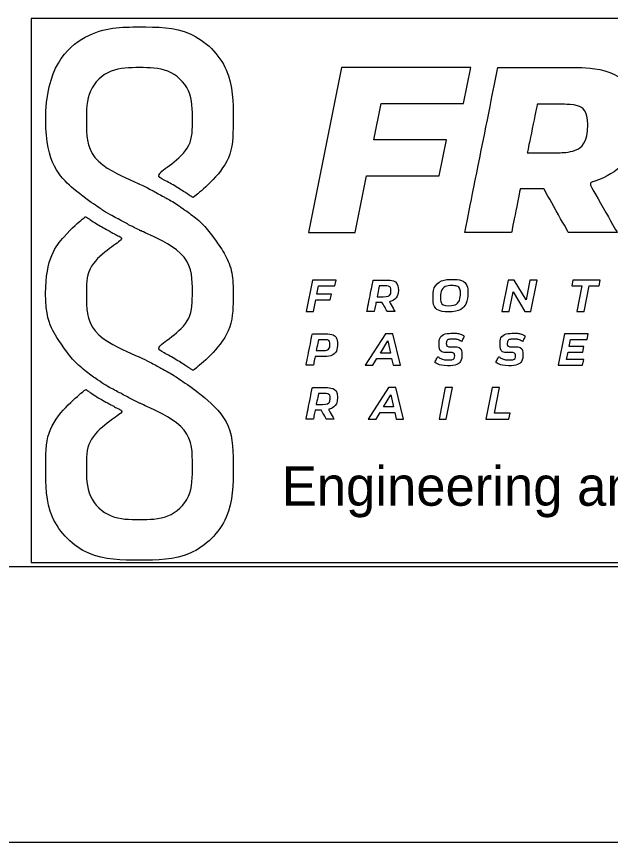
# Model space of a CAD drawing. Extents: x 0 to 1.42, y 0 to 0.92.
# Drawn here: x 0.6182 to 0.7078, y 0 to 0.1247 of the extents above; entities that cross this region are included whole.
import ezdxf

# ---------------------------------------------------------------- set-up
doc = ezdxf.new("R2010")
doc.units = 0
for name, color, linetype in [('DRAFT_Information-No Plot', 7, 'Continuous'), ('DRAFT_Miscellaneous-Blue', 7, 'Continuous'), ('DRAFT_Miscellaneous-Grey', 7, 'Continuous'), ('DRAFT_Miscellaneous-White', 7, 'Continuous'), ('SHEET_Lines', 7, 'Continuous'), ('SHEET_Plot Boundary', 7, 'Continuous')]:
    doc.layers.add(name, color=color, linetype=linetype)

msp = doc.modelspace()

# ---------------------------------------------------------------- linework, layer by layer
at = {"layer": 'DRAFT_Information-No Plot'}
msp.add_lwpolyline([(0.62039, 0.04226), (0.78383, 0.04226), (0.78383, 0.12437), (0.62039, 0.12437), (0.62039, 0.04226)], dxfattribs=at)
at = {"layer": 'DRAFT_Miscellaneous-Blue'}
for p, q in [((0.62258, 0.10897), (0.62258, 0.10897)), ((0.62257, 0.08286), (0.62257, 0.08286))]:
    msp.add_line(p, q, dxfattribs=at)
for points in [[(0.68563, 0.11154), (0.68673, 0.11699), (0.66722, 0.11699), (0.66223, 0.09206), (0.66928, 0.09206), (0.67099, 0.10061), (0.68196, 0.10061), (0.68307, 0.10606), (0.67206, 0.10606), (0.67317, 0.11154)], [(0.66621, 0.08403), (0.66639, 0.08491), (0.66281, 0.08491), (0.66186, 0.08017), (0.66297, 0.08017), (0.66331, 0.0819), (0.6655, 0.0819), (0.66568, 0.08278), (0.66348, 0.08278), (0.66373, 0.08403)], [(0.69563, 0.08491), (0.69504, 0.08194), (0.69327, 0.08491), (0.69236, 0.08491), (0.69141, 0.08017), (0.6925, 0.08017), (0.69309, 0.08314), (0.69486, 0.08017), (0.69576, 0.08017), (0.69671, 0.08491)], [(0.70269, 0.08017), (0.70379, 0.08017), (0.70456, 0.08402), (0.70607, 0.08402), (0.70625, 0.08491), (0.70212, 0.08491), (0.70194, 0.08402), (0.70346, 0.08402)], [(0.675, 0.07205), (0.67609, 0.07205), (0.67493, 0.07679), (0.67384, 0.07679), (0.67078, 0.07205), (0.67195, 0.07205), (0.67256, 0.07306), (0.67477, 0.07306)], [(0.70426, 0.07591), (0.70444, 0.07679), (0.70086, 0.07679), (0.69991, 0.07205), (0.70358, 0.07205), (0.70376, 0.07293), (0.70117, 0.07293), (0.70139, 0.07402), (0.7036, 0.07402), (0.70377, 0.07488), (0.70157, 0.07488), (0.70177, 0.07591)], [(0.67307, 0.07389), (0.67419, 0.07572), (0.67459, 0.07389)], [(0.67547, 0.06392), (0.67656, 0.06392), (0.6754, 0.06866), (0.67432, 0.06866), (0.67125, 0.06392), (0.67242, 0.06392), (0.67304, 0.06493), (0.67524, 0.06493)], [(0.68192, 0.06392), (0.68302, 0.06392), (0.68397, 0.06866), (0.68287, 0.06866)], [(0.68899, 0.06392), (0.69247, 0.06392), (0.69265, 0.06481), (0.69027, 0.06481), (0.69104, 0.06866), (0.68994, 0.06866)], [(0.67354, 0.06577), (0.67466, 0.0676), (0.67506, 0.06577)]]:
    msp.add_lwpolyline(points, close=True, dxfattribs=at)
for points in [[(0.62258, 0.10897), (0.62258, 0.10256), (0.62703, 0.09826), (0.63047, 0.09592), (0.63158, 0.09517), (0.63291, 0.09442), (0.63359, 0.09408), (0.63538, 0.0931), (0.63663, 0.09248), (0.63673, 0.09243), (0.6372, 0.09221), (0.64471, 0.08876), (0.64471, 0.08286), (0.64471, 0.07897), (0.64144, 0.07614), (0.63908, 0.07461), (0.64035, 0.07396), (0.6423, 0.0729), (0.64416, 0.07167), (0.64416, 0.07167), (0.64483, 0.07124), (0.64483, 0.07124), (0.64781, 0.07374), (0.65085, 0.07758), (0.65085, 0.08286), (0.65085, 0.08607), (0.64973, 0.08875), (0.64818, 0.09092), (0.64665, 0.09307), (0.64468, 0.09473), (0.64297, 0.0959), (0.64297, 0.0959), (0.64296, 0.09591), (0.64295, 0.09592), (0.64295, 0.09592), (0.64294, 0.09592), (0.64293, 0.09593), (0.64192, 0.09662), (0.64101, 0.09714), (0.64032, 0.0975), (0.64029, 0.09751), (0.64028, 0.09752), (0.64025, 0.09753), (0.6383, 0.09865), (0.63671, 0.0994), (0.63671, 0.0994), (0.63647, 0.09951), (0.62872, 0.10298), (0.62872, 0.10897), (0.62872, 0.11367), (0.6323, 0.11697), (0.63672, 0.11697), (0.64114, 0.11697), (0.64472, 0.11372), (0.64472, 0.10897), (0.64472, 0.10507), (0.64144, 0.10224), (0.63908, 0.10071), (0.64036, 0.10006), (0.6423, 0.099), (0.64416, 0.09777), (0.64416, 0.09777), (0.64483, 0.09734), (0.64483, 0.09734), (0.64782, 0.09984), (0.65086, 0.10368), (0.65086, 0.10897), (0.65086, 0.1169), (0.64464, 0.12311), (0.63672, 0.12311), (0.62878, 0.12311), (0.62258, 0.1169), (0.62258, 0.10897)], [(0.71148, 0.10905), (0.71148, 0.11403), (0.70781, 0.11699), (0.70144, 0.11699), (0.70144, 0.11699), (0.69079, 0.11699), (0.69079, 0.11699), (0.69079, 0.11699), (0.68581, 0.09206), (0.68581, 0.09206), (0.68581, 0.09206), (0.69286, 0.09206), (0.69286, 0.09206), (0.69286, 0.09206), (0.69417, 0.09869), (0.69417, 0.09869), (0.69417, 0.09869), (0.69774, 0.09869), (0.69774, 0.09869), (0.69774, 0.09869), (0.70144, 0.09206), (0.70144, 0.09206), (0.70144, 0.09206), (0.70881, 0.09206), (0.70881, 0.09206), (0.70881, 0.09206), (0.70457, 0.09954), (0.70457, 0.09954), (0.70892, 0.10104), (0.71148, 0.10445), (0.71148, 0.10905)], [(0.70436, 0.10837), (0.70436, 0.10563), (0.70254, 0.10413), (0.69944, 0.10413), (0.69944, 0.10413), (0.69524, 0.10413), (0.69524, 0.10413), (0.69524, 0.10413), (0.69674, 0.11143), (0.69674, 0.11143), (0.69674, 0.11143), (0.70044, 0.11143), (0.70044, 0.11143), (0.70286, 0.11143), (0.70436, 0.11047), (0.70436, 0.10837)], [(0.62257, 0.08286), (0.62258, 0.07965), (0.62369, 0.07698), (0.62524, 0.07481), (0.62679, 0.07264), (0.62876, 0.07098), (0.63048, 0.0698), (0.63167, 0.06899), (0.63281, 0.06836), (0.63353, 0.06801), (0.63543, 0.06697), (0.63674, 0.06632), (0.63674, 0.06632), (0.63721, 0.06611), (0.64472, 0.06266), (0.64472, 0.05676), (0.64472, 0.05201), (0.64114, 0.04876), (0.63672, 0.04876), (0.6323, 0.04876), (0.62872, 0.05206), (0.62872, 0.05676), (0.62872, 0.06066), (0.63201, 0.0635), (0.63437, 0.06502), (0.63389, 0.06528), (0.6333, 0.06559), (0.63262, 0.06596), (0.63262, 0.06596), (0.63221, 0.06619), (0.63213, 0.06623), (0.63013, 0.06734), (0.62924, 0.06796), (0.62923, 0.06797), (0.62923, 0.06797), (0.62861, 0.0684), (0.62861, 0.0684), (0.62561, 0.0659), (0.62258, 0.06204), (0.62258, 0.05676), (0.62258, 0.04883), (0.62878, 0.04262), (0.63672, 0.04262), (0.64464, 0.04262), (0.65086, 0.04883), (0.65086, 0.05676), (0.65086, 0.06318), (0.64638, 0.06747), (0.64294, 0.06983), (0.64185, 0.07057), (0.64087, 0.07112), (0.64017, 0.07148), (0.63825, 0.07257), (0.63671, 0.07329), (0.63671, 0.07329), (0.63671, 0.07329), (0.62872, 0.07678), (0.62871, 0.08286), (0.62872, 0.08677), (0.632, 0.0896), (0.63437, 0.09113), (0.63383, 0.09141), (0.63315, 0.09177), (0.63237, 0.0922), (0.6302, 0.09339), (0.62924, 0.09406), (0.62923, 0.09406), (0.62923, 0.09406), (0.62859, 0.09449), (0.62859, 0.09449), (0.62561, 0.09199), (0.62258, 0.08814), (0.62257, 0.08286)], [(0.67578, 0.08344), (0.67578, 0.08437), (0.6751, 0.08491), (0.67392, 0.08491), (0.67392, 0.08491), (0.67199, 0.08491), (0.67199, 0.08491), (0.67199, 0.08491), (0.67104, 0.08017), (0.67104, 0.08017), (0.67104, 0.08017), (0.67215, 0.08017), (0.67215, 0.08017), (0.67215, 0.08017), (0.67241, 0.0815), (0.67241, 0.0815), (0.67241, 0.0815), (0.67335, 0.0815), (0.67335, 0.0815), (0.67335, 0.0815), (0.67409, 0.08017), (0.67409, 0.08017), (0.67409, 0.08017), (0.67525, 0.08017), (0.67525, 0.08017), (0.67525, 0.08017), (0.67442, 0.08164), (0.67442, 0.08164), (0.67527, 0.0819), (0.67578, 0.08255), (0.67578, 0.08344)], [(0.68332, 0.08009), (0.68507, 0.08009), (0.68626, 0.08132), (0.68626, 0.08294), (0.68626, 0.08415), (0.68539, 0.08499), (0.68395, 0.08499), (0.6822, 0.08499), (0.68101, 0.08377), (0.68101, 0.08215), (0.68101, 0.08093), (0.68188, 0.08009), (0.68332, 0.08009)], [(0.67351, 0.08237), (0.67351, 0.08237), (0.67258, 0.08237), (0.67258, 0.08237), (0.67258, 0.08237), (0.67291, 0.08402), (0.67291, 0.08402), (0.67291, 0.08402), (0.67378, 0.08402), (0.67378, 0.08402), (0.67434, 0.08402), (0.67467, 0.0838), (0.67467, 0.08334), (0.67467, 0.08271), (0.67424, 0.08237), (0.67351, 0.08237)], [(0.68342, 0.08103), (0.68258, 0.08103), (0.68212, 0.08151), (0.68212, 0.08221), (0.68212, 0.08321), (0.68278, 0.08406), (0.68385, 0.08406), (0.68468, 0.08406), (0.68515, 0.08358), (0.68515, 0.08287), (0.68515, 0.08187), (0.68449, 0.08103), (0.68342, 0.08103)], [(0.66473, 0.07679), (0.66473, 0.07679), (0.66281, 0.07679), (0.66281, 0.07679), (0.66281, 0.07679), (0.66186, 0.07205), (0.66186, 0.07205), (0.66186, 0.07205), (0.66297, 0.07205), (0.66297, 0.07205), (0.66297, 0.07205), (0.66322, 0.07335), (0.66322, 0.07335), (0.66322, 0.07335), (0.66428, 0.07335), (0.66428, 0.07335), (0.66569, 0.07335), (0.66658, 0.0741), (0.66658, 0.07531), (0.66658, 0.07624), (0.66591, 0.07679), (0.66473, 0.07679)], [(0.68318, 0.07196), (0.68451, 0.07196), (0.68537, 0.07259), (0.68537, 0.07358), (0.68537, 0.07503), (0.68301, 0.07463), (0.68302, 0.0754), (0.68302, 0.07574), (0.68339, 0.07599), (0.68403, 0.07599), (0.6845, 0.07599), (0.68496, 0.07587), (0.68532, 0.07562), (0.68532, 0.07562), (0.68573, 0.07646), (0.68573, 0.07646), (0.68532, 0.07672), (0.68473, 0.07687), (0.68409, 0.07687), (0.68278, 0.07687), (0.68193, 0.07624), (0.68193, 0.07526), (0.68193, 0.07375), (0.68428, 0.07416), (0.68428, 0.0734), (0.68428, 0.07305), (0.6839, 0.07284), (0.68329, 0.07284), (0.68273, 0.07284), (0.68216, 0.07302), (0.68173, 0.07334), (0.68173, 0.07334), (0.68128, 0.07249), (0.68128, 0.07249), (0.68168, 0.07219), (0.68241, 0.07196), (0.68318, 0.07196)], [(0.69238, 0.07196), (0.6937, 0.07196), (0.69457, 0.07259), (0.69457, 0.07358), (0.69457, 0.07503), (0.69221, 0.07463), (0.69222, 0.0754), (0.69222, 0.07574), (0.69259, 0.07599), (0.69323, 0.07599), (0.6937, 0.07599), (0.69416, 0.07587), (0.69452, 0.07562), (0.69452, 0.07562), (0.69493, 0.07646), (0.69493, 0.07646), (0.69452, 0.07672), (0.69393, 0.07687), (0.69329, 0.07687), (0.69198, 0.07687), (0.69112, 0.07624), (0.69112, 0.07526), (0.69112, 0.07375), (0.69347, 0.07416), (0.69347, 0.0734), (0.69347, 0.07305), (0.69309, 0.07284), (0.69249, 0.07284), (0.69193, 0.07284), (0.69136, 0.07302), (0.69093, 0.07334), (0.69093, 0.07334), (0.69048, 0.07249), (0.69048, 0.07249), (0.69088, 0.07219), (0.69161, 0.07196), (0.69238, 0.07196)], [(0.66433, 0.07425), (0.66433, 0.07425), (0.6634, 0.07425), (0.6634, 0.07425), (0.6634, 0.07425), (0.66373, 0.07589), (0.66373, 0.07589), (0.66373, 0.07589), (0.66459, 0.07589), (0.66459, 0.07589), (0.66515, 0.07589), (0.66547, 0.07568), (0.66547, 0.07521), (0.66547, 0.07458), (0.66505, 0.07425), (0.66433, 0.07425)], [(0.66659, 0.06719), (0.66659, 0.06812), (0.66592, 0.06866), (0.66474, 0.06866), (0.66474, 0.06866), (0.66281, 0.06866), (0.66281, 0.06866), (0.66281, 0.06866), (0.66186, 0.06392), (0.66186, 0.06392), (0.66186, 0.06392), (0.66297, 0.06392), (0.66297, 0.06392), (0.66297, 0.06392), (0.66323, 0.06525), (0.66323, 0.06525), (0.66323, 0.06525), (0.66416, 0.06525), (0.66416, 0.06525), (0.66416, 0.06525), (0.66491, 0.06392), (0.66491, 0.06392), (0.66491, 0.06392), (0.66607, 0.06392), (0.66607, 0.06392), (0.66607, 0.06392), (0.66524, 0.06538), (0.66524, 0.06538), (0.66609, 0.06565), (0.66659, 0.06629), (0.66659, 0.06719)], [(0.66433, 0.06612), (0.66433, 0.06612), (0.6634, 0.06612), (0.6634, 0.06612), (0.6634, 0.06612), (0.66373, 0.06777), (0.66373, 0.06777), (0.66373, 0.06777), (0.6646, 0.06777), (0.6646, 0.06777), (0.66516, 0.06777), (0.66548, 0.06755), (0.66548, 0.06709), (0.66548, 0.06646), (0.66506, 0.06612), (0.66433, 0.06612)]]:
    msp.add_open_spline(points, degree=3, dxfattribs=at)
at = {"layer": 'DRAFT_Miscellaneous-White'}
for points in [[(0.68563, 0.11154), (0.68673, 0.11699), (0.66722, 0.11699), (0.66223, 0.09206), (0.66928, 0.09206), (0.67099, 0.10061), (0.68196, 0.10061), (0.68307, 0.10606), (0.67206, 0.10606), (0.67317, 0.11154), (0.68563, 0.11154)], [(0.66621, 0.08403), (0.66639, 0.08491), (0.66281, 0.08491), (0.66186, 0.08017), (0.66297, 0.08017), (0.66331, 0.0819), (0.6655, 0.0819), (0.66568, 0.08278), (0.66348, 0.08278), (0.66373, 0.08403), (0.66621, 0.08403)], [(0.69563, 0.08491), (0.69504, 0.08194), (0.69327, 0.08491), (0.69236, 0.08491), (0.69141, 0.08017), (0.6925, 0.08017), (0.69309, 0.08314), (0.69486, 0.08017), (0.69576, 0.08017), (0.69671, 0.08491), (0.69563, 0.08491)], [(0.70269, 0.08017), (0.70379, 0.08017), (0.70456, 0.08402), (0.70607, 0.08402), (0.70625, 0.08491), (0.70212, 0.08491), (0.70194, 0.08402), (0.70346, 0.08402), (0.70269, 0.08017)], [(0.675, 0.07205), (0.67609, 0.07205), (0.67493, 0.07679), (0.67384, 0.07679), (0.67078, 0.07205), (0.67195, 0.07205), (0.67256, 0.07306), (0.67477, 0.07306), (0.675, 0.07205)], [(0.70426, 0.07591), (0.70444, 0.07679), (0.70086, 0.07679), (0.69991, 0.07205), (0.70358, 0.07205), (0.70376, 0.07293), (0.70117, 0.07293), (0.70139, 0.07402), (0.7036, 0.07402), (0.70377, 0.07488), (0.70157, 0.07488), (0.70177, 0.07591), (0.70426, 0.07591)], [(0.67307, 0.07389), (0.67419, 0.07572), (0.67459, 0.07389), (0.67307, 0.07389)], [(0.67547, 0.06392), (0.67656, 0.06392), (0.6754, 0.06866), (0.67432, 0.06866), (0.67125, 0.06392), (0.67242, 0.06392), (0.67304, 0.06493), (0.67524, 0.06493), (0.67547, 0.06392)], [(0.68192, 0.06392), (0.68302, 0.06392), (0.68397, 0.06866), (0.68287, 0.06866), (0.68192, 0.06392)], [(0.68899, 0.06392), (0.69247, 0.06392), (0.69265, 0.06481), (0.69027, 0.06481), (0.69104, 0.06866), (0.68994, 0.06866), (0.68899, 0.06392)], [(0.67354, 0.06577), (0.67466, 0.0676), (0.67506, 0.06577), (0.67354, 0.06577)]]:
    msp.add_lwpolyline(points, dxfattribs=at)
for points in [[(0.62258, 0.10897), (0.62258, 0.10256), (0.62703, 0.09826), (0.63047, 0.09592), (0.63158, 0.09517), (0.63291, 0.09442), (0.63359, 0.09408), (0.63538, 0.0931), (0.63663, 0.09248), (0.63673, 0.09243), (0.6372, 0.09221), (0.64471, 0.08876), (0.64471, 0.08286), (0.64471, 0.07897), (0.64144, 0.07614), (0.63908, 0.07461), (0.64035, 0.07396), (0.6423, 0.0729), (0.64416, 0.07167), (0.64416, 0.07167), (0.64483, 0.07124), (0.64483, 0.07124), (0.64781, 0.07374), (0.65085, 0.07758), (0.65085, 0.08286), (0.65085, 0.08607), (0.64973, 0.08875), (0.64818, 0.09092), (0.64665, 0.09307), (0.64468, 0.09473), (0.64297, 0.0959), (0.64297, 0.0959), (0.64296, 0.09591), (0.64295, 0.09592), (0.64295, 0.09592), (0.64294, 0.09592), (0.64293, 0.09593), (0.64192, 0.09662), (0.64101, 0.09714), (0.64032, 0.0975), (0.64029, 0.09751), (0.64028, 0.09752), (0.64025, 0.09753), (0.6383, 0.09865), (0.63671, 0.0994), (0.63671, 0.0994), (0.63647, 0.09951), (0.62872, 0.10298), (0.62872, 0.10897), (0.62872, 0.11367), (0.6323, 0.11697), (0.63672, 0.11697), (0.64114, 0.11697), (0.64472, 0.11372), (0.64472, 0.10897), (0.64472, 0.10507), (0.64144, 0.10224), (0.63908, 0.10071), (0.64036, 0.10006), (0.6423, 0.099), (0.64416, 0.09777), (0.64416, 0.09777), (0.64483, 0.09734), (0.64483, 0.09734), (0.64782, 0.09984), (0.65086, 0.10368), (0.65086, 0.10897), (0.65086, 0.1169), (0.64464, 0.12311), (0.63672, 0.12311), (0.62878, 0.12311), (0.62258, 0.1169), (0.62258, 0.10897)], [(0.71148, 0.10905), (0.71148, 0.11403), (0.70781, 0.11699), (0.70144, 0.11699), (0.70144, 0.11699), (0.69079, 0.11699), (0.69079, 0.11699), (0.69079, 0.11699), (0.68581, 0.09206), (0.68581, 0.09206), (0.68581, 0.09206), (0.69286, 0.09206), (0.69286, 0.09206), (0.69286, 0.09206), (0.69417, 0.09869), (0.69417, 0.09869), (0.69417, 0.09869), (0.69774, 0.09869), (0.69774, 0.09869), (0.69774, 0.09869), (0.70144, 0.09206), (0.70144, 0.09206), (0.70144, 0.09206), (0.70881, 0.09206), (0.70881, 0.09206), (0.70881, 0.09206), (0.70457, 0.09954), (0.70457, 0.09954), (0.70892, 0.10104), (0.71148, 0.10445), (0.71148, 0.10905)], [(0.70436, 0.10837), (0.70436, 0.10563), (0.70254, 0.10413), (0.69944, 0.10413), (0.69944, 0.10413), (0.69524, 0.10413), (0.69524, 0.10413), (0.69524, 0.10413), (0.69674, 0.11143), (0.69674, 0.11143), (0.69674, 0.11143), (0.70044, 0.11143), (0.70044, 0.11143), (0.70286, 0.11143), (0.70436, 0.11047), (0.70436, 0.10837)], [(0.62257, 0.08286), (0.62258, 0.07965), (0.62369, 0.07698), (0.62524, 0.07481), (0.62679, 0.07264), (0.62876, 0.07098), (0.63048, 0.0698), (0.63167, 0.06899), (0.63281, 0.06836), (0.63353, 0.06801), (0.63543, 0.06697), (0.63674, 0.06632), (0.63674, 0.06632), (0.63721, 0.06611), (0.64472, 0.06266), (0.64472, 0.05676), (0.64472, 0.05201), (0.64114, 0.04876), (0.63672, 0.04876), (0.6323, 0.04876), (0.62872, 0.05206), (0.62872, 0.05676), (0.62872, 0.06066), (0.63201, 0.0635), (0.63437, 0.06502), (0.63389, 0.06528), (0.6333, 0.06559), (0.63262, 0.06596), (0.63262, 0.06596), (0.63221, 0.06619), (0.63213, 0.06623), (0.63013, 0.06734), (0.62924, 0.06796), (0.62923, 0.06797), (0.62923, 0.06797), (0.62861, 0.0684), (0.62861, 0.0684), (0.62561, 0.0659), (0.62258, 0.06204), (0.62258, 0.05676), (0.62258, 0.04883), (0.62878, 0.04262), (0.63672, 0.04262), (0.64464, 0.04262), (0.65086, 0.04883), (0.65086, 0.05676), (0.65086, 0.06318), (0.64638, 0.06747), (0.64294, 0.06983), (0.64185, 0.07057), (0.64087, 0.07112), (0.64017, 0.07148), (0.63825, 0.07257), (0.63671, 0.07329), (0.63671, 0.07329), (0.63671, 0.07329), (0.62872, 0.07678), (0.62871, 0.08286), (0.62872, 0.08677), (0.632, 0.0896), (0.63437, 0.09113), (0.63383, 0.09141), (0.63315, 0.09177), (0.63237, 0.0922), (0.6302, 0.09339), (0.62924, 0.09406), (0.62923, 0.09406), (0.62923, 0.09406), (0.62859, 0.09449), (0.62859, 0.09449), (0.62561, 0.09199), (0.62258, 0.08814), (0.62257, 0.08286)], [(0.67578, 0.08344), (0.67578, 0.08437), (0.6751, 0.08491), (0.67392, 0.08491), (0.67392, 0.08491), (0.67199, 0.08491), (0.67199, 0.08491), (0.67199, 0.08491), (0.67104, 0.08017), (0.67104, 0.08017), (0.67104, 0.08017), (0.67215, 0.08017), (0.67215, 0.08017), (0.67215, 0.08017), (0.67241, 0.0815), (0.67241, 0.0815), (0.67241, 0.0815), (0.67335, 0.0815), (0.67335, 0.0815), (0.67335, 0.0815), (0.67409, 0.08017), (0.67409, 0.08017), (0.67409, 0.08017), (0.67525, 0.08017), (0.67525, 0.08017), (0.67525, 0.08017), (0.67442, 0.08164), (0.67442, 0.08164), (0.67527, 0.0819), (0.67578, 0.08255), (0.67578, 0.08344)], [(0.68332, 0.08009), (0.68507, 0.08009), (0.68626, 0.08132), (0.68626, 0.08294), (0.68626, 0.08415), (0.68539, 0.08499), (0.68395, 0.08499), (0.6822, 0.08499), (0.68101, 0.08377), (0.68101, 0.08215), (0.68101, 0.08093), (0.68188, 0.08009), (0.68332, 0.08009)], [(0.67351, 0.08237), (0.67351, 0.08237), (0.67258, 0.08237), (0.67258, 0.08237), (0.67258, 0.08237), (0.67291, 0.08402), (0.67291, 0.08402), (0.67291, 0.08402), (0.67378, 0.08402), (0.67378, 0.08402), (0.67434, 0.08402), (0.67467, 0.0838), (0.67467, 0.08334), (0.67467, 0.08271), (0.67424, 0.08237), (0.67351, 0.08237)], [(0.68342, 0.08103), (0.68258, 0.08103), (0.68212, 0.08151), (0.68212, 0.08221), (0.68212, 0.08321), (0.68278, 0.08406), (0.68385, 0.08406), (0.68468, 0.08406), (0.68515, 0.08358), (0.68515, 0.08287), (0.68515, 0.08187), (0.68449, 0.08103), (0.68342, 0.08103)], [(0.66473, 0.07679), (0.66473, 0.07679), (0.66281, 0.07679), (0.66281, 0.07679), (0.66281, 0.07679), (0.66186, 0.07205), (0.66186, 0.07205), (0.66186, 0.07205), (0.66297, 0.07205), (0.66297, 0.07205), (0.66297, 0.07205), (0.66322, 0.07335), (0.66322, 0.07335), (0.66322, 0.07335), (0.66428, 0.07335), (0.66428, 0.07335), (0.66569, 0.07335), (0.66658, 0.0741), (0.66658, 0.07531), (0.66658, 0.07624), (0.66591, 0.07679), (0.66473, 0.07679)], [(0.68318, 0.07196), (0.68451, 0.07196), (0.68537, 0.07259), (0.68537, 0.07358), (0.68537, 0.07503), (0.68301, 0.07463), (0.68302, 0.0754), (0.68302, 0.07574), (0.68339, 0.07599), (0.68403, 0.07599), (0.6845, 0.07599), (0.68496, 0.07587), (0.68532, 0.07562), (0.68532, 0.07562), (0.68573, 0.07646), (0.68573, 0.07646), (0.68532, 0.07672), (0.68473, 0.07687), (0.68409, 0.07687), (0.68278, 0.07687), (0.68193, 0.07624), (0.68193, 0.07526), (0.68193, 0.07375), (0.68428, 0.07416), (0.68428, 0.0734), (0.68428, 0.07305), (0.6839, 0.07284), (0.68329, 0.07284), (0.68273, 0.07284), (0.68216, 0.07302), (0.68173, 0.07334), (0.68173, 0.07334), (0.68128, 0.07249), (0.68128, 0.07249), (0.68168, 0.07219), (0.68241, 0.07196), (0.68318, 0.07196)], [(0.69238, 0.07196), (0.6937, 0.07196), (0.69457, 0.07259), (0.69457, 0.07358), (0.69457, 0.07503), (0.69221, 0.07463), (0.69222, 0.0754), (0.69222, 0.07574), (0.69259, 0.07599), (0.69323, 0.07599), (0.6937, 0.07599), (0.69416, 0.07587), (0.69452, 0.07562), (0.69452, 0.07562), (0.69493, 0.07646), (0.69493, 0.07646), (0.69452, 0.07672), (0.69393, 0.07687), (0.69329, 0.07687), (0.69198, 0.07687), (0.69112, 0.07624), (0.69112, 0.07526), (0.69112, 0.07375), (0.69347, 0.07416), (0.69347, 0.0734), (0.69347, 0.07305), (0.69309, 0.07284), (0.69249, 0.07284), (0.69193, 0.07284), (0.69136, 0.07302), (0.69093, 0.07334), (0.69093, 0.07334), (0.69048, 0.07249), (0.69048, 0.07249), (0.69088, 0.07219), (0.69161, 0.07196), (0.69238, 0.07196)], [(0.66433, 0.07425), (0.66433, 0.07425), (0.6634, 0.07425), (0.6634, 0.07425), (0.6634, 0.07425), (0.66373, 0.07589), (0.66373, 0.07589), (0.66373, 0.07589), (0.66459, 0.07589), (0.66459, 0.07589), (0.66515, 0.07589), (0.66547, 0.07568), (0.66547, 0.07521), (0.66547, 0.07458), (0.66505, 0.07425), (0.66433, 0.07425)], [(0.66659, 0.06719), (0.66659, 0.06812), (0.66592, 0.06866), (0.66474, 0.06866), (0.66474, 0.06866), (0.66281, 0.06866), (0.66281, 0.06866), (0.66281, 0.06866), (0.66186, 0.06392), (0.66186, 0.06392), (0.66186, 0.06392), (0.66297, 0.06392), (0.66297, 0.06392), (0.66297, 0.06392), (0.66323, 0.06525), (0.66323, 0.06525), (0.66323, 0.06525), (0.66416, 0.06525), (0.66416, 0.06525), (0.66416, 0.06525), (0.66491, 0.06392), (0.66491, 0.06392), (0.66491, 0.06392), (0.66607, 0.06392), (0.66607, 0.06392), (0.66607, 0.06392), (0.66524, 0.06538), (0.66524, 0.06538), (0.66609, 0.06565), (0.66659, 0.06629), (0.66659, 0.06719)], [(0.66433, 0.06612), (0.66433, 0.06612), (0.6634, 0.06612), (0.6634, 0.06612), (0.6634, 0.06612), (0.66373, 0.06777), (0.66373, 0.06777), (0.66373, 0.06777), (0.6646, 0.06777), (0.6646, 0.06777), (0.66516, 0.06777), (0.66548, 0.06755), (0.66548, 0.06709), (0.66548, 0.06646), (0.66506, 0.06612), (0.66433, 0.06612)]]:
    msp.add_open_spline(points, degree=3, dxfattribs=at)
at = {"layer": 'SHEET_Lines'}
msp.add_line((0.08333, 0.04167), (1.375, 0.04167), dxfattribs=at)
at = {"layer": 'SHEET_Plot Boundary'}
msp.add_lwpolyline([(0, 0.91666), (1.41666, 0.91666), (1.41666, 0), (0, 0)], close=True, dxfattribs=at)

# ---------------------------------------------------------------- texts
at = {"layer": 'DRAFT_Miscellaneous-Grey'}
msp.add_text('Engineering and Design', height=0.0059343, dxfattribs=at).set_placement((0.65819, 0.05083))

doc.saveas('drawing.dxf')
